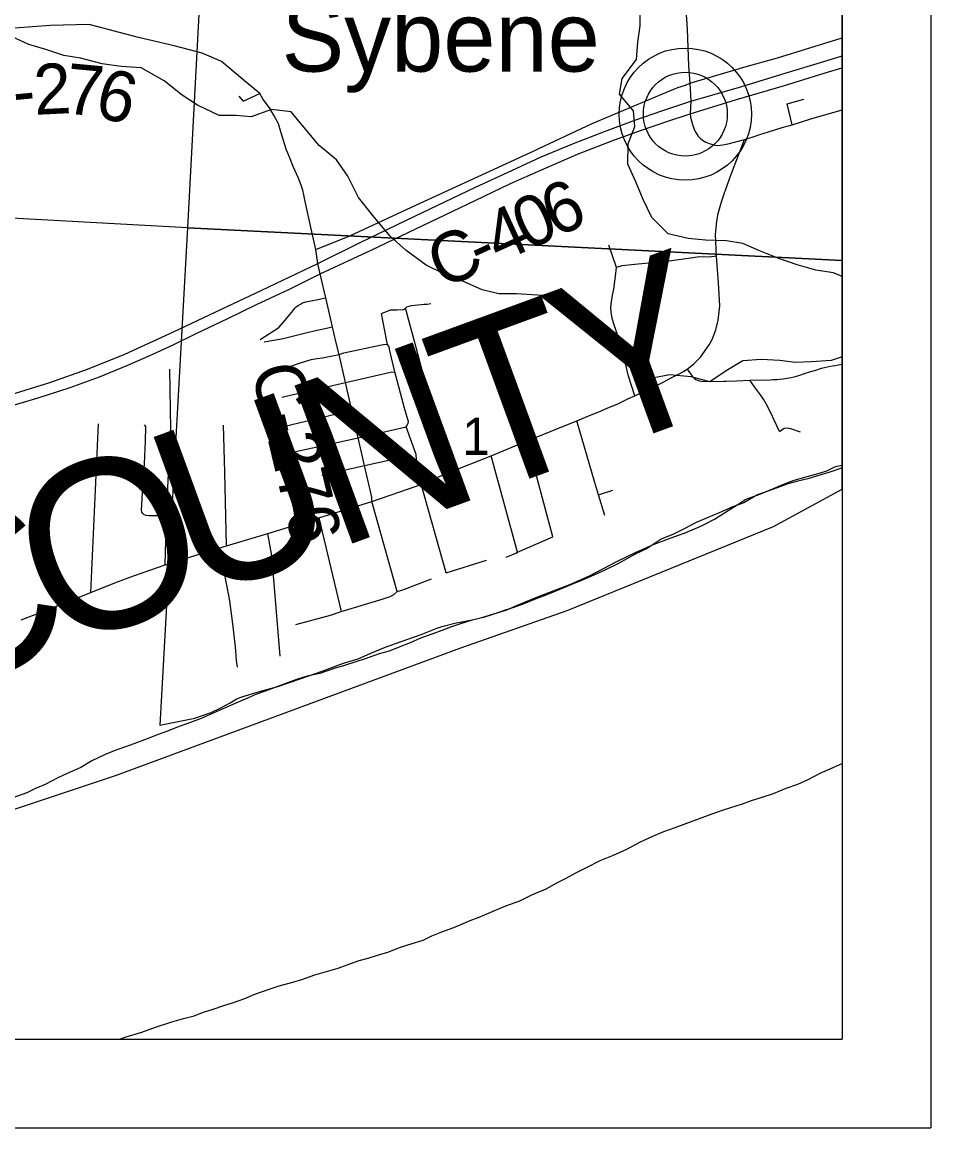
# Model space of a CAD drawing. Extents: x 0 to 45.4, y -2.2 to 22.
# Drawn here: x 7.977 to 9, y 14 to 15.245 of the extents above; entities that cross this region are included whole.
import ezdxf

# ---------------------------------------------------------------- set-up
doc = ezdxf.new("R2010")
doc.units = 0
for name, color, linetype in [('GM_X_Corporation', 7, 'Continuous'), ('GM_X_County_Road', 7, 'Continuous'), ('GM_X_County_Road_Text', 7, 'Continuous'), ('GM_X_County_Text', 7, 'Continuous'), ('GM_X_Major_River', 7, 'Continuous'), ('GM_X_Minor_River', 7, 'Continuous'), ('GM_X_Section_Text', 7, 'Continuous'), ('GM_X_Township_Road', 7, 'Continuous'), ('GM_X_Township_Road_Text', 7, 'Continuous'), ('GM_X_Unincorporated', 7, 'Continuous'), ('GM_X_Unincorporated_Location', 7, 'Continuous'), ('GM_X_Unincorporated_Text', 7, 'Continuous'), ('GM_X_US_Route', 7, 'Continuous'), ('SH_Data', 7, 'Continuous')]:
    doc.layers.add(name, color=color, linetype=linetype)

msp = doc.modelspace()

# ---------------------------------------------------------------- linework, layer by layer
at = {"layer": 'GM_X_Corporation'}
for points in [[(5.6021, 14.1), (7.0413, 14.1), (7.1146, 14.1136), (7.5608, 14.2194), (7.6244, 14.2444), (8.0832, 14.3972), (8.4711, 14.5406), (8.5907, 14.5823), (8.8228, 14.6772), (8.9, 14.7192), (8.9, 20.9), (2.1, 20.9)], [(5.6021, 14.1), (7.0413, 14.1), (7.1146, 14.1136), (7.5608, 14.2194), (7.6244, 14.2444), (8.0832, 14.3972), (8.4711, 14.5406), (8.5907, 14.5823), (8.8228, 14.6772), (8.9, 14.7192), (8.9, 20.9), (6.2942, 20.9), (6.2882, 20.8226), (6.2789, 20.7002), (6.2588, 20.2929), (6.2538, 20.2076), (6.2346, 20.0088), (6.2236, 19.8542), (6.181, 19.2539), (6.1763, 19.1885), (6.1061, 18.1607), (5.642, 18.1908)]]:
    msp.add_lwpolyline(points, dxfattribs=at)
for points in [[(7.1036, 16.0876), (8.2164, 16.0186), (8.1634, 15.0131), (7.0412, 15.0748)], [(8.9, 14.9765), (8.9, 15.9811), (8.2164, 16.0186), (8.1634, 15.0131)], [(8.9, 14.746), (8.9, 14.9765), (8.1634, 15.0131), (8.132, 14.4535), (8.1714, 14.4614), (8.19, 14.4678), (8.2002, 14.4724), (8.2112, 14.4784), (8.218, 14.4826), (8.2245, 14.4853), (8.2442, 14.4913), (8.265, 14.497), (8.29, 14.5057), (8.315, 14.514), (8.3389, 14.5231), (8.3552, 14.528), (8.3696, 14.5344), (8.3852, 14.5408), (8.3973, 14.5454), (8.4261, 14.5556), (8.445, 14.5628), (8.4526, 14.5651), (8.464, 14.5681), (8.4837, 14.5719), (8.4947, 14.5745), (8.5117, 14.5798), (8.5227, 14.5832), (8.5356, 14.5889), (8.5583, 14.5983), (8.5936, 14.6119), (8.6156, 14.6214), (8.6474, 14.6381), (8.6683, 14.6483), (8.6887, 14.6573), (8.7046, 14.663), (8.724, 14.6702), (8.741, 14.6774), (8.7566, 14.6853), (8.7789, 14.6997), (8.7857, 14.7035), (8.7911, 14.7073), (8.8085, 14.7137), (8.8354, 14.7251), (8.846, 14.7292), (8.8756, 14.7376), (8.8828, 14.7398), (8.8911, 14.744), (8.8945, 14.7451)]]:
    msp.add_lwpolyline(points, close=True, dxfattribs=at)
at = {"layer": 'GM_X_County_Road'}
for points in [[(8.7243, 15.2592), (8.7256, 15.2369), (8.7273, 15.1957), (8.7287, 15.1762), (8.7299, 15.1559), (8.729, 15.1415)], [(8.7896, 15.1941), (8.8275, 15.2045), (8.9, 15.227)], [(8.7287, 15.1762), (8.7808, 15.1917), (8.7896, 15.1941)], [(8.3077, 14.9889), (8.346, 15.0042), (8.4153, 15.0366), (8.555, 15.1006), (8.5579, 15.1022), (8.5589, 15.1026), (8.6188, 15.1306), (8.6971, 15.1639), (8.7151, 15.1713), (8.7239, 15.174), (8.7287, 15.1762)], [(8.729, 15.1415), (8.7293, 15.1378), (8.7317, 15.1295), (8.734, 15.1232), (8.7353, 15.1206), (8.7378, 15.117), (8.7403, 15.1144), (8.743, 15.112), (8.7467, 15.1098), (8.7506, 15.1081), (8.7531, 15.1073), (8.7569, 15.1063), (8.76, 15.106), (8.7659, 15.1067), (8.7733, 15.1083), (8.7904, 15.1128)], [(8.7904, 15.1128), (8.7998, 15.1157), (8.8075, 15.1184), (8.8172, 15.1215), (8.8328, 15.1261), (8.8438, 15.1294), (8.8649, 15.1358), (8.9, 15.1461)], [(8.6505, 14.8166), (8.6597, 14.821), (8.6667, 14.8243), (8.6773, 14.8293), (8.6911, 14.8359), (8.6995, 14.84), (8.7071, 14.844), (8.7168, 14.8488), (8.7217, 14.8516), (8.7255, 14.8541), (8.7329, 14.8597), (8.7407, 14.8676), (8.7505, 14.8816), (8.7537, 14.8877), (8.7579, 14.8985), (8.7606, 14.9093), (8.7626, 14.9253), (8.7608, 14.9513), (8.7586, 14.9813), (8.7574, 15.0059), (8.759, 15.0209), (8.7604, 15.0294), (8.7642, 15.0427), (8.7674, 15.0516), (8.7748, 15.0725), (8.7904, 15.1128)], [(8.3709, 14.7051), (8.3709, 14.7102), (8.3625, 14.7456), (8.3552, 14.7769), (8.3482, 14.8081), (8.3412, 14.8393), (8.3339, 14.8705), (8.3304, 14.8853), (8.3263, 14.9019), (8.3189, 14.9346), (8.3127, 14.9614)], [(7.9762, 14.5719), (7.9937, 14.5788), (8.0177, 14.5881), (8.0259, 14.5914), (8.0543, 14.6027), (8.0833, 14.6142), (8.1037, 14.6219), (8.138, 14.6339), (8.1405, 14.6347), (8.162, 14.6415), (8.1838, 14.6482), (8.192, 14.6507), (8.1985, 14.6528), (8.2071, 14.6553), (8.2536, 14.6691), (8.311, 14.6867), (8.3709, 14.7051), (8.4228, 14.7233), (8.4262, 14.7247), (8.4576, 14.7379), (8.5049, 14.7565), (8.5455, 14.7735), (8.6015, 14.7959), (8.6114, 14.8001), (8.629, 14.8073), (8.6364, 14.8105), (8.6468, 14.8149), (8.6505, 14.8166)]]:
    msp.add_lwpolyline(points, dxfattribs=at)
at = {"layer": 'GM_X_Major_River'}
for points in [[(8.9, 14.7433), (8.8994, 14.7428), (8.8862, 14.7382), (8.876, 14.7352), (8.8616, 14.7307), (8.8503, 14.728), (8.8389, 14.725), (8.8268, 14.7204), (8.8166, 14.717), (8.8049, 14.7125), (8.7894, 14.7038), (8.7777, 14.6996), (8.7618, 14.6924), (8.7474, 14.6863), (8.7357, 14.6814), (8.7232, 14.6749), (8.7103, 14.6685), (8.6963, 14.6628), (8.6805, 14.6522), (8.6672, 14.6458), (8.6476, 14.6351), (8.6332, 14.6279), (8.6173, 14.6207), (8.6067, 14.6162), (8.5946, 14.6113), (8.5768, 14.6037), (8.5666, 14.5999), (8.5545, 14.5953), (8.5417, 14.59), (8.5307, 14.5859), (8.5209, 14.5828), (8.5069, 14.5779), (8.4963, 14.5745), (8.4838, 14.5715), (8.4706, 14.5673), (8.4603, 14.5639), (8.4494, 14.5601), (8.4395, 14.5563), (8.4256, 14.5514), (8.4138, 14.5461), (8.4021, 14.5415), (8.3904, 14.5366), (8.379, 14.5336), (8.3632, 14.5279), (8.3529, 14.5245), (8.3401, 14.5207), (8.3284, 14.5173), (8.3121, 14.5116), (8.2981, 14.5086), (8.286, 14.5048), (8.2758, 14.501), (8.2637, 14.4964), (8.2508, 14.4915), (8.241, 14.4881), (8.2308, 14.4839), (8.2202, 14.4794), (8.2055, 14.4729), (8.1888, 14.4654), (8.1786, 14.4608)], [(8.1786, 14.4608), (8.1654, 14.4559), (8.151, 14.4506), (8.1408, 14.4468), (8.1302, 14.443), (8.1177, 14.4381), (8.106, 14.4335), (8.0946, 14.4294), (8.0825, 14.4252), (8.0697, 14.4199), (8.0557, 14.4134), (8.0432, 14.4059), (8.0277, 14.399), (8.0175, 14.3941), (8.0031, 14.3865), (7.9922, 14.382), (7.9823, 14.3771), (7.9668, 14.3714)], [(8.0868, 14.1), (8.0942, 14.1025), (8.1119, 14.1078), (8.1271, 14.1134), (8.1456, 14.1195), (8.1588, 14.1233), (8.1706, 14.1263), (8.1811, 14.1301), (8.1921, 14.1335), (8.2042, 14.1377), (8.2152, 14.1411), (8.2277, 14.1456), (8.239, 14.1506), (8.2553, 14.1563), (8.2666, 14.16), (8.2817, 14.1642), (8.292, 14.1669), (8.3067, 14.1722), (8.3196, 14.176), (8.3328, 14.1797), (8.343, 14.1835), (8.3566, 14.1885), (8.3665, 14.1911), (8.377, 14.1945), (8.3888, 14.1979), (8.4031, 14.2036), (8.416, 14.2074), (8.4285, 14.2112), (8.4383, 14.2161), (8.4497, 14.2207), (8.4629, 14.2256), (8.4814, 14.2335), (8.4916, 14.2373), (8.5075, 14.2438), (8.5215, 14.2498), (8.5374, 14.2555), (8.551, 14.2624), (8.5669, 14.2692), (8.5798, 14.2764), (8.5896, 14.2813), (8.6002, 14.287), (8.613, 14.2934), (8.6278, 14.301), (8.6429, 14.3071), (8.6577, 14.3139), (8.6732, 14.3222), (8.6872, 14.3283), (8.6996, 14.3336), (8.7121, 14.3381), (8.7254, 14.3431), (8.7397, 14.3484), (8.7526, 14.3533), (8.7666, 14.3579), (8.7878, 14.3647), (8.798, 14.3685), (8.8089, 14.3719), (8.8229, 14.3764), (8.8373, 14.3825), (8.8502, 14.387), (8.8619, 14.3923), (8.8755, 14.3995), (8.8865, 14.4041), (8.8982, 14.4094), (8.9, 14.4102)]]:
    msp.add_lwpolyline(points, dxfattribs=at)
at = {"layer": 'GM_X_Minor_River'}
for points in [[(8.9, 14.9584), (8.8903, 14.9625), (8.8706, 14.9656), (8.8494, 14.9718), (8.829, 14.9787), (8.8063, 14.9879), (8.7882, 14.9956), (8.77, 14.9987), (8.7465, 14.9995), (8.7269, 15.0011), (8.7042, 15.0065), (8.6861, 15.0248), (8.6763, 15.0453), (8.668, 15.0651), (8.659, 15.0849), (8.6591, 15.1077), (8.6668, 15.1274), (8.6654, 15.1449), (8.6495, 15.1639), (8.6526, 15.1814), (8.6686, 15.2026), (8.6702, 15.2223), (8.6726, 15.2405), (8.6726, 15.258)], [(8.9, 14.8679), (8.8876, 14.8638), (8.8656, 14.8624), (8.8474, 14.8617), (8.83, 14.8641), (8.8088, 14.8649), (8.7884, 14.8634), (8.7694, 14.8521), (8.7512, 14.84), (8.73, 14.8454), (8.7058, 14.8478), (8.6868, 14.8441), (8.6687, 14.8647), (8.6537, 14.886), (8.6325, 14.905), (8.6129, 14.915), (8.5955, 14.9181), (8.5759, 14.9364), (8.5509, 14.938), (8.5335, 14.9388), (8.5138, 14.9389), (8.4949, 14.9435), (8.4707, 14.9542), (8.451, 14.9619), (8.4321, 14.9711), (8.4095, 14.9879), (8.3914, 15.0039), (8.3733, 15.0252), (8.3559, 15.0473), (8.3439, 15.0716), (8.3311, 15.0899), (8.3115, 15.1059), (8.2942, 15.1265), (8.2799, 15.144), (8.2579, 15.1464), (8.2351, 15.1381), (8.2177, 15.1397), (8.1988, 15.1398), (8.1746, 15.1513), (8.1572, 15.1627), (8.1369, 15.1787), (8.1112, 15.1933), (8.0885, 15.1949), (8.0673, 15.198), (8.043, 15.2042), (8.0241, 15.2073), (8.0037, 15.2142), (7.9848, 15.2196), (7.9651, 15.2288)]]:
    msp.add_lwpolyline(points, dxfattribs=at)
at = {"layer": 'GM_X_Township_Road'}
for p, q in [((8.8384, 15.1527), (8.8571, 15.1581)), ((8.8438, 15.1294), (8.8384, 15.1527)), ((8.6463, 14.9685), (8.6374, 14.9939)), ((8.3873, 14.8876), (8.3817, 14.9167)), ((8.2713, 14.7896), (8.3482, 14.8081)), ((8.0543, 14.6027), (8.0632, 14.7927)), ((8.6214, 14.7276), (8.6015, 14.7959)), ((8.5745, 14.6655), (8.5455, 14.7735)), ((8.5346, 14.648), (8.5049, 14.7565)), ((8.4544, 14.6248), (8.4262, 14.7247)), ((8.6257, 14.7126), (8.6419, 14.7179)), ((8.3991, 14.604), (8.3709, 14.7051)), ((8.311, 14.6867), (8.3364, 14.5815)), ((8.4544, 14.6248), (8.4999, 14.6393))]:
    msp.add_line(p, q, dxfattribs=at)
for points in [[(8.3127, 14.9614), (8.31, 14.9731), (8.3077, 14.9889), (8.3031, 15.0087), (8.2957, 15.0428), (8.2942, 15.0506), (8.293, 15.0556), (8.2916, 15.0601), (8.29, 15.0644), (8.2878, 15.0699), (8.2824, 15.0825), (8.2781, 15.0928), (8.2745, 15.102), (8.2685, 15.1214), (8.2656, 15.1302), (8.2637, 15.1338), (8.2631, 15.1352), (8.2604, 15.1403), (8.2581, 15.144), (8.2556, 15.1483), (8.2486, 15.1578), (8.2446, 15.1644), (8.2252, 15.1806), (8.2014, 15.2004), (8.1798, 15.21), (8.1483, 15.2181), (8.1082, 15.2277), (8.0527, 15.2422), (8.0088, 15.2409), (7.9485, 15.2364)], [(8.2209, 15.1614), (8.226, 15.156), (8.2446, 15.1644)], [(8.7586, 14.9813), (8.7505, 14.9803), (8.7396, 14.9807), (8.7322, 14.9795), (8.7055, 14.9756)], [(8.6667, 14.8243), (8.6596, 14.8464), (8.6566, 14.859), (8.6526, 14.8736), (8.6486, 14.8881), (8.6453, 14.8983), (8.6432, 14.9051), (8.6416, 14.9101), (8.6408, 14.9138), (8.6401, 14.9181), (8.6398, 14.9243), (8.6405, 14.93), (8.6418, 14.9375), (8.6433, 14.9441), (8.645, 14.9588), (8.6463, 14.9685)], [(8.7055, 14.9756), (8.6667, 14.9719), (8.652, 14.9706), (8.6463, 14.9685)], [(8.2449, 14.8875), (8.266, 14.9012), (8.2709, 14.9067), (8.2807, 14.9185), (8.2829, 14.9215), (8.2846, 14.9233), (8.2861, 14.9247), (8.288, 14.9259), (8.2903, 14.9272), (8.2927, 14.9287), (8.2963, 14.93), (8.3002, 14.9309), (8.3084, 14.9322), (8.3181, 14.9343)], [(8.3817, 14.9167), (8.3919, 14.9208), (8.3994, 14.9211), (8.4064, 14.9213), (8.4087, 14.9229), (8.4103, 14.9242), (8.4153, 14.9257), (8.4192, 14.9264), (8.4224, 14.9266), (8.4266, 14.927), (8.4296, 14.9272), (8.4332, 14.9275), (8.4373, 14.9282)], [(8.4576, 14.7379), (8.4206, 14.8786), (8.4087, 14.9229)], [(8.2497, 14.8851), (8.2689, 14.8884), (8.2756, 14.8899), (8.2859, 14.8924), (8.2965, 14.8952), (8.3057, 14.8973), (8.3263, 14.9019)], [(8.2698, 14.854), (8.2892, 14.8608), (8.2965, 14.8632), (8.3026, 14.8649), (8.3092, 14.8662), (8.3154, 14.8668), (8.3339, 14.8705), (8.3394, 14.8726), (8.3816, 14.8814), (8.3862, 14.8822), (8.3884, 14.8818)], [(8.4093, 14.7893), (8.4107, 14.791), (8.4118, 14.7933), (8.4119, 14.7952), (8.4114, 14.7974), (8.4076, 14.8103), (8.3966, 14.851), (8.3911, 14.8747), (8.3904, 14.8788), (8.3899, 14.88), (8.3884, 14.8818), (8.3873, 14.8876)], [(8.1443, 14.7846), (8.1444, 14.7866), (8.1433, 14.8542)], [(8.7255, 14.8541), (8.7313, 14.8461), (8.7338, 14.8438), (8.7355, 14.8427), (8.7373, 14.8416), (8.7386, 14.8413)], [(8.8222, 14.8425), (8.8265, 14.8427), (8.8337, 14.8434), (8.8426, 14.8448), (8.8462, 14.8456), (8.8512, 14.8472), (8.8577, 14.8493), (8.8647, 14.8514), (8.8706, 14.8532), (8.877, 14.8552), (8.8819, 14.8564), (8.8851, 14.857), (8.8892, 14.8578), (8.8921, 14.8584), (8.8958, 14.859), (8.8961, 14.859), (8.9, 14.8597), (8.9, 14.8597)], [(8.2693, 14.8228), (8.3412, 14.8393), (8.3917, 14.8507), (8.3966, 14.851)], [(8.7386, 14.8413), (8.7392, 14.8411), (8.7418, 14.8407), (8.7464, 14.8404), (8.7665, 14.8407), (8.7696, 14.8408)], [(8.7696, 14.8408), (8.7816, 14.8412), (8.7962, 14.8417), (8.8193, 14.8423), (8.8222, 14.8425)], [(8.8296, 14.784), (8.8237, 14.7968), (8.8203, 14.8043), (8.8146, 14.8153), (8.8117, 14.8203), (8.8082, 14.8253), (8.8014, 14.8341), (8.7962, 14.8417)], [(8.1396, 14.6884), (8.1318, 14.6887), (8.129, 14.689), (8.1243, 14.689), (8.1203, 14.6889), (8.1167, 14.6894), (8.1145, 14.6903), (8.1129, 14.6916), (8.1117, 14.6933), (8.1115, 14.6953), (8.1129, 14.7213), (8.1148, 14.7478), (8.1159, 14.7727), (8.1163, 14.7896), (8.115, 14.7916)], [(8.2071, 14.6553), (8.2054, 14.7382), (8.2037, 14.7912)], [(8.2765, 14.7595), (8.3552, 14.7769), (8.4093, 14.7893)], [(8.4228, 14.7233), (8.4206, 14.758), (8.4093, 14.7893)], [(8.138, 14.6339), (8.1396, 14.6884), (8.1443, 14.7846)], [(8.8296, 14.784), (8.8349, 14.7876), (8.8383, 14.7883), (8.8421, 14.7874), (8.853, 14.7835)], [(8.3144, 14.735), (8.3625, 14.7456), (8.4087, 14.7558), (8.4137, 14.7567)], [(8.6329, 14.6896), (8.6257, 14.7126), (8.6214, 14.7276)], [(8.2677, 14.5312), (8.2587, 14.64), (8.258, 14.6461), (8.2536, 14.6691)], [(8.522, 14.6425), (8.5327, 14.6471), (8.5346, 14.648), (8.5745, 14.6655)], [(8.2194, 14.5188), (8.2184, 14.5267), (8.2174, 14.5414), (8.2143, 14.5673), (8.2108, 14.5934), (8.2095, 14.6013), (8.2083, 14.6074), (8.2036, 14.6321), (8.1985, 14.6528)], [(8.2852, 14.5667), (8.3243, 14.5772), (8.3364, 14.5815), (8.3824, 14.5952), (8.3915, 14.5983), (8.3953, 14.6001), (8.3991, 14.604), (8.4055, 14.6057), (8.4378, 14.6183)]]:
    msp.add_lwpolyline(points, dxfattribs=at)
at = {"layer": 'GM_X_Unincorporated'}
for radius in [0.0744, 0.0472]:
    msp.add_circle((8.7236, 15.1413), radius, dxfattribs=at)
at = {"layer": 'GM_X_Unincorporated_Location'}
msp.add_line((8.7236, 15.1413), (8.7236, 15.1413), dxfattribs=at)
at = {"layer": 'GM_X_US_Route'}
for points in [[(7.9658, 14.8261), (8.0084, 14.8392), (8.0508, 14.8541), (8.0928, 14.8712), (8.1477, 14.8962), (8.2015, 14.9218), (8.2468, 14.9432), (8.31, 14.9731), (8.3578, 14.9968), (8.4193, 15.0264), (8.4874, 15.0589), (8.5284, 15.0779), (8.5614, 15.0931), (8.5978, 15.1082), (8.6325, 15.1217), (8.6669, 15.1344), (8.6971, 15.1449), (8.7299, 15.1559), (8.7871, 15.1725), (8.8371, 15.1878), (8.8794, 15.2006), (8.9, 15.2069)], [(8.2675, 14.9392), (8.2775, 14.9439), (8.3127, 14.9614), (8.3709, 14.9886), (8.428, 15.0159), (8.4869, 15.0439), (8.5269, 15.063), (8.5608, 15.0781), (8.6024, 15.0962), (8.644, 15.1123), (8.6741, 15.1232), (8.7027, 15.1329), (8.729, 15.1415), (8.7814, 15.1576), (8.8353, 15.1737), (8.8847, 15.1888), (8.9, 15.1935)], [(7.9622, 14.8121), (7.9952, 14.8218), (8.0311, 14.8335), (8.0642, 14.8455), (8.0961, 14.8588), (8.1201, 14.8692), (8.1471, 14.8817), (8.1732, 14.8944), (8.2088, 14.9111), (8.241, 14.9268), (8.2675, 14.9392)]]:
    msp.add_lwpolyline(points, dxfattribs=at)
at = {"layer": 'SH_Data'}
for p, q in [((9, 21), (9, 14)), ((8.9, 20.9), (8.9, 14.1)), ((2.1, 14.1), (8.9, 14.1)), ((2, 14), (9, 14))]:
    msp.add_line(p, q, dxfattribs=at)

# ---------------------------------------------------------------- texts
at = {"layer": 'GM_X_County_Road_Text'}
for s, height, rotation, p in [('6', 0.0568, 23.961, (8.5774, 15.0019)), ('0', 0.0568, 24.4887, (8.5457, 14.9874)), ('4', 0.0568, 24.5791, (8.5139, 14.9729)), ('C', 0.0568, 24.6132, (8.4503, 14.9437)), ('-', 0.0568, 24.6088, (8.4927, 14.9631)), ('C-276', 0.05682, 283.3713, (8.2347, 14.8543))]:
    msp.add_text(s, height=height, rotation=rotation, dxfattribs=at).set_placement(p)
at = {"layer": 'GM_X_County_Text'}
for s, rotation, p in [('Y', 20.0779, (8.6196, 14.7569)), ('T', 20.078, (8.4866, 14.7083)), ('N', 20.0779, (8.3293, 14.6507)), ('U', 20.0781, (8.1719, 14.5932)), ('O', 20.0779, (8.0146, 14.5357)), ('C', 20.0779, (7.8698, 14.4828))]:
    msp.add_text(s, height=0.1894, rotation=rotation, dxfattribs=at).set_placement(p)
at = {"layer": 'GM_X_Section_Text'}
msp.add_text('1', height=0.0419, rotation=0, dxfattribs=at).set_placement((8.4725, 14.7577))
at = {"layer": 'GM_X_Township_Road_Text'}
for s, rotation, p in [('2', 2.8362, (7.9914, 15.1404)), ('7', 354.6594, (8.0242, 15.1422)), ('6', 345.6826, (8.0567, 15.1394)), ('-', 5.4829, (7.9689, 15.1383))]:
    msp.add_text(s, height=0.0568, rotation=rotation, dxfattribs=at).set_placement(p)
at = {"layer": 'GM_X_Unincorporated_Text'}
msp.add_text('Sybene', height=0.07898, rotation=0, dxfattribs=at).set_placement((8.2692, 15.1892))

doc.saveas('drawing.dxf')
